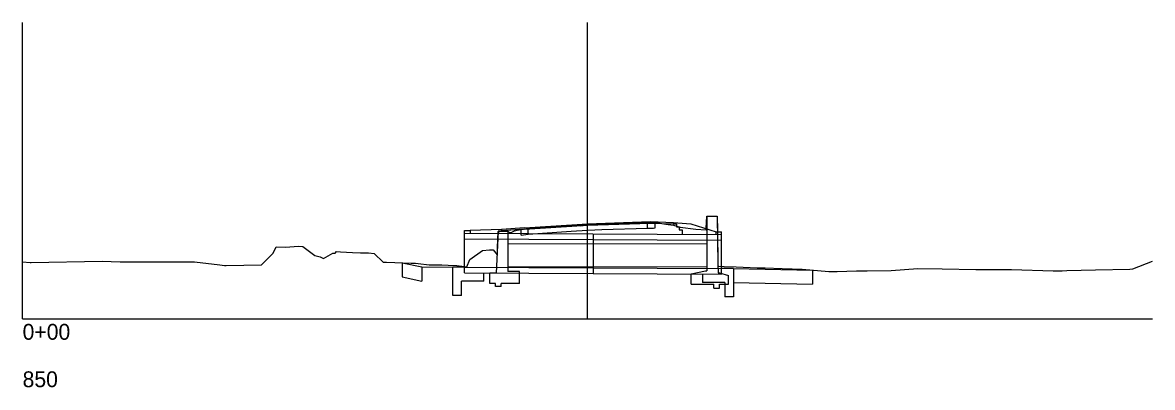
# Model space of a CAD drawing. Extents: x 223098 to 226975, y 386666 to 387582.
# Drawn here: x 224988.9 to 225188.9, y 387129.4 to 387194 of the extents above; entities that cross this region are included whole.
import ezdxf

# ---------------------------------------------------------------- set-up
doc = ezdxf.new("R2010")
doc.units = 0
for name, color, linetype in [('_CIVIL_CONSTRUCTION', 7, 'Continuous'), ('Default', 7, 'Continuous'), ('GE_P_Alignment_100_Bearings', 7, 'Continuous'), ('GE_P_Alignment_100_Cardinal_Points', 7, 'Continuous'), ('PV_X_COP', 7, 'Continuous'), ('PV_X_Shoulder', 7, 'Continuous'), ('PV_X_Shoulder_Aggregate', 7, 'Continuous'), ('SV_X_LiDAR_Check_Spots', 7, 'Continuous'), ('UT_X_Telecom_Cells', 7, 'Continuous')]:
    doc.layers.add(name, color=color, linetype=linetype)

msp = doc.modelspace()

# ---------------------------------------------------------------- linework, layer by layer
at = {"layer": '_CIVIL_CONSTRUCTION'}
for p, q in [((225110.06, 387159.67), (225110.06, 387150)), ((225110.06, 387159.67), (225111.89, 387159.67)), ((225073.14, 387157.05), (225072.8, 387149.59)), ((225074.86, 387157.05), (225073.14, 387157.05)), ((225074.86, 387157.05), (225074.86, 387149.92)), ((225074.86, 387154.87), (225110.06, 387154.81)), ((225074.86, 387150.75), (225110.06, 387150.69)), ((225107.32, 387149.5), (225109.81, 387150)), ((225109.81, 387150), (225110.06, 387150)), ((225072.8, 387149.59), (225071.65, 387149.59)), ((225071.65, 387147.74), (225071.65, 387149.59)), ((225076.92, 387149.92), (225074.86, 387149.92)), ((225076.92, 387147.74), (225076.92, 387149.92)), ((225107.32, 387147.67), (225107.32, 387149.5)), ((225112.05, 387149.67), (225112.3, 387149.67)), ((225112.3, 387149.67), (225113.92, 387149.17)), ((225113.92, 387147.67), (225113.92, 387149.17)), ((225072.63, 387147.74), (225071.65, 387147.74)), ((225072.63, 387147.24), (225072.63, 387147.74)), ((225073.63, 387147.24), (225072.63, 387147.24)), ((225076.92, 387147.74), (225073.63, 387147.74)), ((225073.63, 387147.24), (225073.63, 387147.74)), ((225107.32, 387147.67), (225111.32, 387147.67)), ((225111.32, 387146.92), (225111.32, 387147.67)), ((225111.32, 387146.92), (225112.32, 387146.92)), ((225112.32, 387146.92), (225112.32, 387147.67)), ((225112.32, 387147.67), (225113.92, 387147.67))]:
    msp.add_line(p, q, dxfattribs=at)
msp.add_lwpolyline([(225111.89, 387159.67), (225112.02, 387151.15), (225112.05, 387149.67)], dxfattribs=at)
at = {"layer": 'Default'}
for p, q in [((224988.94, 387141.5), (224988.94, 387193.97)), ((225088.94, 387141.5), (225088.94, 387193.97)), ((224988.94, 387141.5), (225188.94, 387141.5))]:
    msp.add_line(p, q, dxfattribs=at)
at = {"layer": 'GE_P_Alignment_100_Bearings'}
msp.add_lwpolyline([(224988.94, 387151.59), (224990.28, 387151.47), (224990.29, 387151.47), (224990.45, 387151.47), (225003.02, 387151.71), (225006.21, 387151.61), (225017.5, 387151.58), (225018.94, 387151.58), (225019.35, 387151.59), (225023.85, 387151.07), (225024.71, 387150.98), (225024.81, 387150.96), (225024.87, 387150.96), (225025, 387150.96), (225031.24, 387151.08), (225033.32, 387153.14), (225033.8, 387154.26), (225035.53, 387154.18), (225037.74, 387154.36), (225038.55, 387154.3), (225040.67, 387152.73), (225041.6, 387152.47), (225042.23, 387152.17), (225043.87, 387153.15), (225044.26, 387153.13), (225044.48, 387153.42), (225045.22, 387153.39), (225047.35, 387153.25), (225048.73, 387153.2), (225050.2, 387153.22), (225051.18, 387153.09), (225052.78, 387151.56), (225052.84, 387151.54), (225053.33, 387151.52), (225057.72, 387151.37), (225058.5, 387151.37), (225058.94, 387151.33), (225060.94, 387151.1), (225063.14, 387151.06), (225064.3, 387151.03), (225065.79, 387150.95), (225067.58, 387150.74), (225068.1, 387152.01), (225070.34, 387153.61), (225071.6, 387153.74), (225072.24, 387153.75), (225072.97, 387152.83), (225072.98, 387153.56), (225072.99, 387154.13), (225073.14, 387157), (225074.06, 387157.03), (225074.86, 387157.05), (225074.94, 387156.89), (225075.18, 387156.78), (225075.57, 387156.88), (225076.01, 387157.07), (225076.51, 387157.2), (225077.17, 387157.35), (225077.61, 387157.4), (225078.42, 387157.49), (225086.04, 387158.05), (225088.94, 387158.24), (225089.02, 387158.24), (225091.46, 387158.33), (225099.54, 387158.59), (225100.63, 387158.59), (225100.89, 387158.6), (225101.12, 387158.56), (225102.8, 387158.27), (225103.2, 387158.2), (225104.15, 387158.1), (225105.35, 387157.73), (225108.1, 387157.38), (225109.94, 387157.3), (225109.94, 387157.59), (225110.06, 387159.67), (225111.71, 387159.67), (225111.89, 387159.67), (225111.96, 387157.2), (225112.02, 387151.15), (225112.05, 387150.8), (225112.14, 387150.84), (225113.13, 387150.78), (225115.27, 387150.73), (225118.96, 387150.54), (225120.4, 387150.54), (225123.41, 387150.44), (225126.94, 387150.28), (225131.65, 387149.92), (225133.16, 387149.9), (225136.56, 387150.04), (225138.45, 387150), (225142.7, 387150.07), (225147.42, 387150.4), (225151.74, 387150.38), (225157.68, 387150.26), (225163.98, 387150.22), (225171.37, 387150.04), (225172.98, 387150.04), (225173.81, 387150.06), (225178.86, 387150.16), (225184.95, 387150.28), (225185.5, 387150.34), (225188.94, 387151.71)], dxfattribs=at)
at = {"layer": 'GE_P_Alignment_100_Cardinal_Points'}
for p, q in [((225099.54, 387157.59), (225099.54, 387158.59)), ((225100.89, 387157.6), (225100.89, 387158.6)), ((225077.17, 387156.35), (225077.17, 387157.35)), ((225078.42, 387156.49), (225078.42, 387157.49))]:
    msp.add_line(p, q, dxfattribs=at)
msp.add_lwpolyline([(225077.17, 387156.35), (225077.17, 387156.35), (225077.61, 387156.4), (225078.42, 387156.49), (225086.04, 387157.05), (225088.94, 387157.24), (225089.02, 387157.24), (225091.46, 387157.33), (225099.54, 387157.59), (225100.63, 387157.59), (225100.89, 387157.6)], dxfattribs=at)
at = {"layer": 'PV_X_COP'}
for p, q in [((225114.77, 387150.43), (225114.77, 387145.43)), ((225109.27, 387149.45), (225109.27, 387147.93)), ((225113.27, 387147.93), (225109.27, 387147.93)), ((225113.27, 387147.93), (225113.27, 387145.43)), ((225114.77, 387145.43), (225113.27, 387145.43))]:
    msp.add_line(p, q, dxfattribs=at)
at = {"layer": 'PV_X_Shoulder'}
for p, q in [((225056.15, 387151.42), (225056.15, 387148.92)), ((225056.15, 387151.42), (225059.63, 387150.69)), ((225059.63, 387150.69), (225059.63, 387148.19)), ((225114.77, 387150.43), (225128.77, 387150.14)), ((225128.77, 387150.14), (225128.77, 387147.64)), ((225056.15, 387148.92), (225059.63, 387148.19)), ((225114.77, 387147.93), (225128.77, 387147.64))]:
    msp.add_line(p, q, dxfattribs=at)
at = {"layer": 'PV_X_Shoulder_Aggregate'}
for p, q in [((225067.19, 387156.66), (225067.19, 387157.16)), ((225067.19, 387157.16), (225068.19, 387157.16)), ((225067.19, 387156.66), (225112.69, 387156.43)), ((225067.19, 387149.66), (225067.19, 387156.66)), ((225068.19, 387157.16), (225068.19, 387156.65)), ((225089.94, 387156.54), (225089.94, 387149.54)), ((225111.69, 387156.44), (225111.69, 387156.93)), ((225111.69, 387156.93), (225112.69, 387156.93)), ((225112.69, 387149.43), (225112.69, 387156.93)), ((225067.19, 387155.66), (225112.69, 387155.43)), ((225065.11, 387145.66), (225065.11, 387150.66)), ((225067.19, 387150.66), (225065.11, 387150.66)), ((225067.19, 387150.66), (225112.69, 387150.43)), ((225114.77, 387150.43), (225112.69, 387150.43)), ((225070.61, 387148.16), (225066.61, 387148.16)), ((225066.61, 387145.66), (225066.61, 387148.16)), ((225067.19, 387149.66), (225112.69, 387149.43)), ((225070.61, 387148.16), (225070.61, 387149.64)), ((225066.61, 387145.66), (225065.11, 387145.66))]:
    msp.add_line(p, q, dxfattribs=at)
at = {"layer": 'SV_X_LiDAR_Check_Spots'}
for p, q in [((225077.77, 387157.61), (225088.94, 387158.34)), ((225077.77, 387157.36), (225088.94, 387158.09)), ((225087.65, 387158), (225087.65, 387158.25)), ((225087.65, 387158), (225088.15, 387158.04)), ((225088.94, 387158.34), (225100.11, 387158.73)), ((225088.94, 387158.09), (225100.11, 387158.48)), ((225100.11, 387158.73), (225104.17, 387158.59)), ((225100.11, 387158.48), (225104.17, 387158.34)), ((225104.17, 387158.59), (225104.17, 387158.34)), ((225104.17, 387158.34), (225104.67, 387158.32)), ((225104.67, 387158.32), (225104.67, 387157.82)), ((225073.71, 387157.34), (225068.19, 387157.16)), ((225073.71, 387157.09), (225073.21, 387157.05)), ((225073.21, 387157.05), (225073.21, 387156.63)), ((225077.77, 387157.61), (225073.71, 387157.34)), ((225077.77, 387157.36), (225073.71, 387157.09)), ((225073.71, 387157.34), (225073.71, 387157.09)), ((225104.67, 387157.82), (225105.17, 387157.8)), ((225105.17, 387157.8), (225105.17, 387157.3)), ((225105.17, 387157.3), (225105.67, 387157.29)), ((225105.67, 387157.29), (225105.67, 387156.47))]:
    msp.add_line(p, q, dxfattribs=at)
at = {"layer": 'UT_X_Telecom_Cells'}
for p, q in [((225104.17, 387158.59), (225107.21, 387158.33)), ((225107.21, 387158.33), (225111.69, 387156.93)), ((225059.63, 387150.69), (225065.11, 387150.66))]:
    msp.add_line(p, q, dxfattribs=at)

# ---------------------------------------------------------------- texts
at = {"layer": 'Default'}
for s, p in [('0+00', (224988.94, 387137.81)), ('850', (224988.94, 387129.41))]:
    msp.add_text(s, height=2.8, dxfattribs=at).set_placement(p)

doc.saveas('drawing.dxf')
